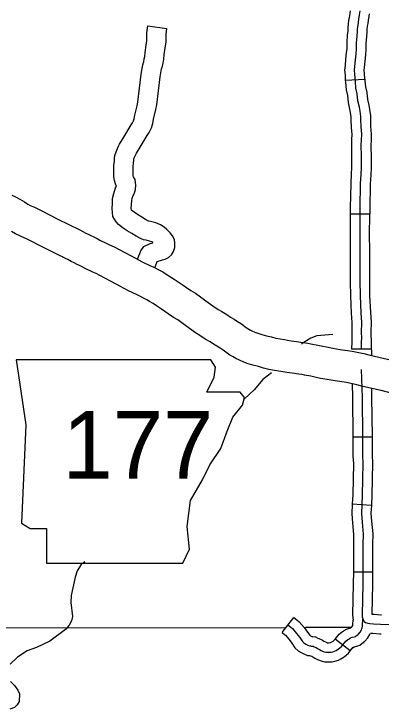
# Model space of a CAD drawing. Extents: x 1377389 to 1380723, y 1168351 to 1170484.
# Drawn here: x 1378723.7 to 1378781, y 1169308.4 to 1169417.1 of the extents above; entities that cross this region are included whole.
import ezdxf

# ---------------------------------------------------------------- set-up
doc = ezdxf.new("R2010")
doc.units = 0
doc.layers.add('B_Fill', color=7, linetype='Continuous')

msp = doc.modelspace()

# ---------------------------------------------------------------- linework, layer by layer
at = {"layer": 'B_Fill'}
for p, q in [((1378775.48, 1169406.7), (1378778.48, 1169406.87)), ((1378778.48, 1169406.87), (1378778.48, 1169406.87)), ((1378779.25, 1169385.74), (1378776.25, 1169385.76)), ((1378733.53, 1169383.52), (1378733.61, 1169383.48)), ((1378731.3, 1169379.05), (1378731.38, 1169379.01)), ((1378779.47, 1169364.62), (1378776.47, 1169364.66)), ((1378776.61, 1169350.92), (1378779.61, 1169350.92)), ((1378776.52, 1169340.44), (1378779.51, 1169340.28)), ((1378776.69, 1169329.83), (1378779.69, 1169329.81)), ((1378765.55, 1169320.37), (1378767.41, 1169322.72)), ((1378776.2, 1169317.48), (1378773.84, 1169319.33))]:
    msp.add_line(p, q, dxfattribs=at)
for points in [[(1378775.48, 1169406.7), (1378775.44, 1169407.5), (1378775.36, 1169408.26), (1378775.44, 1169409.01), (1378775.54, 1169409.97), (1378775.64, 1169410.95), (1378775.7, 1169411.64), (1378775.7, 1169412.61), (1378775.8, 1169413.73), (1378775.86, 1169414.39), (1378775.86, 1169414.81), (1378775.94, 1169415.51), (1378776.01, 1169416), (1378776.08, 1169416.47), (1378776.18, 1169417.14), (1378776.24, 1169417.52)], [(1378777.97, 1169364.64), (1378777.98, 1169365.8), (1378778, 1169366.4), (1378777.98, 1169367.27), (1378778, 1169368.83), (1378777.9, 1169370.33), (1378777.79, 1169373), (1378777.76, 1169375.35), (1378777.76, 1169378.87), (1378777.76, 1169380.2), (1378777.73, 1169382.39), (1378777.76, 1169386.73), (1378777.83, 1169390.48), (1378777.92, 1169391.99), (1378777.96, 1169392.97), (1378777.96, 1169393.66), (1378777.96, 1169394.69), (1378777.93, 1169396.58), (1378777.96, 1169397.34), (1378777.99, 1169398.24), (1378777.89, 1169399.4), (1378777.86, 1169400.53), (1378777.86, 1169401.03), (1378777.73, 1169401.85), (1378777.63, 1169402.49), (1378777.4, 1169403.45), (1378777.3, 1169404.54), (1378777.1, 1169405.44), (1378777, 1169406.5), (1378776.93, 1169407.63), (1378776.87, 1169408.26), (1378776.93, 1169408.85), (1378777.03, 1169409.82), (1378777.13, 1169410.81), (1378777.2, 1169411.57), (1378777.2, 1169412.54), (1378777.3, 1169413.6), (1378777.36, 1169414.33), (1378777.36, 1169414.72), (1378777.43, 1169415.32), (1378777.5, 1169415.79), (1378777.56, 1169416.25), (1378777.66, 1169416.91), (1378777.76, 1169417.54)], [(1378778.48, 1169406.87), (1378778.43, 1169407.75), (1378778.37, 1169408.25), (1378778.42, 1169408.69), (1378778.52, 1169409.66), (1378778.62, 1169410.67), (1378778.7, 1169411.51), (1378778.7, 1169412.47), (1378778.79, 1169413.46), (1378778.86, 1169414.26), (1378778.86, 1169414.64), (1378778.92, 1169415.13), (1378778.98, 1169415.57), (1378779.05, 1169416.03), (1378779.14, 1169416.69), (1378779.2, 1169417.06)], [(1378742.99, 1169378.69), (1378743.19, 1169379.23), (1378743.33, 1169379.61), (1378743.5, 1169380.04), (1378743.98, 1169380.68), (1378744.98, 1169381.14), (1378745.39, 1169381.27), (1378745.35, 1169381.3), (1378745.19, 1169381.4), (1378744.86, 1169381.54), (1378744.35, 1169381.67), (1378743.9, 1169381.76), (1378743.43, 1169381.96), (1378742.77, 1169382.3), (1378742.1, 1169382.71), (1378741.37, 1169383.16), (1378740.75, 1169383.57), (1378740, 1169384.11), (1378739.64, 1169384.56), (1378739.11, 1169385.41), (1378739.01, 1169386.63), (1378739.06, 1169387.41), (1378739.08, 1169388.19), (1378739.26, 1169388.98), (1378739.53, 1169389.88), (1378739.68, 1169390.13), (1378739.68, 1169390.15), (1378739.57, 1169390.32), (1378739.38, 1169391.01), (1378739.28, 1169391.58), (1378739.28, 1169392.31), (1378739.3, 1169393.34), (1378739.37, 1169394.03), (1378739.39, 1169394.47), (1378739.46, 1169394.91), (1378739.62, 1169395.5), (1378739.84, 1169396.04), (1378740.02, 1169396.38), (1378740.15, 1169396.69), (1378740.83, 1169397.78), (1378741.98, 1169399.71), (1378742.2, 1169400.02), (1378742.35, 1169400.34), (1378742.45, 1169400.65), (1378742.55, 1169401.23), (1378742.93, 1169402.71), (1378743.02, 1169403.27), (1378743.57, 1169407.61), (1378743.8, 1169409.1), (1378743.95, 1169409.64), (1378744.04, 1169410.02), (1378744.13, 1169410.4), (1378744.17, 1169411.02), (1378744.35, 1169412.16), (1378744.44, 1169412.85), (1378744.44, 1169413.39), (1378744.44, 1169414.1), (1378744.6, 1169415.21), (1378747.57, 1169414.77)], [(1378745.7, 1169377.37), (1378746, 1169378.2), (1378746.05, 1169378.33), (1378746.07, 1169378.34), (1378746.86, 1169378.59), (1378747.3, 1169378.71), (1378747.84, 1169378.98), (1378748.31, 1169379.4), (1378748.58, 1169379.9), (1378748.8, 1169380.56), (1378748.8, 1169381.21), (1378748.75, 1169381.78), (1378748.45, 1169382.37), (1378748.09, 1169382.85), (1378747.55, 1169383.36), (1378747.13, 1169383.73), (1378746.57, 1169384.08), (1378745.83, 1169384.38), (1378745.01, 1169384.6), (1378744.76, 1169384.65), (1378744.7, 1169384.68), (1378744.24, 1169384.91), (1378743.67, 1169385.26), (1378742.98, 1169385.69), (1378742.45, 1169386.04), (1378742.09, 1169386.3), (1378742.04, 1169386.38), (1378742.01, 1169386.67), (1378742.05, 1169387.26), (1378742.07, 1169387.82), (1378742.16, 1169388.23), (1378742.29, 1169388.66), (1378742.38, 1169388.8), (1378742.58, 1169389.26), (1378742.64, 1169389.62), (1378742.71, 1169390.26), (1378742.6, 1169391.15), (1378742.34, 1169391.56), (1378742.31, 1169391.67), (1378742.28, 1169391.85), (1378742.28, 1169392.27), (1378742.3, 1169393.16), (1378742.36, 1169393.8), (1378742.38, 1169394.16), (1378742.4, 1169394.3), (1378742.47, 1169394.55), (1378742.56, 1169394.76), (1378742.73, 1169395.09), (1378742.82, 1169395.31), (1378743.39, 1169396.22), (1378744.5, 1169398.07), (1378744.81, 1169398.52), (1378745.15, 1169399.26), (1378745.37, 1169399.93), (1378745.48, 1169400.6), (1378745.86, 1169402.09), (1378745.99, 1169402.82), (1378746.54, 1169407.2), (1378746.74, 1169408.46), (1378746.86, 1169408.9), (1378746.96, 1169409.34), (1378747.11, 1169409.97), (1378747.15, 1169410.69), (1378747.32, 1169411.73), (1378747.44, 1169412.66), (1378747.44, 1169413.39), (1378747.44, 1169413.88), (1378747.57, 1169414.77)], [(1378776.43, 1169396.28), (1378776.43, 1169396.6), (1378776.46, 1169397.4), (1378776.49, 1169398.2), (1378776.39, 1169399.31), (1378776.36, 1169400.51), (1378776.36, 1169400.91), (1378776.25, 1169401.62), (1378776.16, 1169402.19), (1378775.91, 1169403.2), (1378775.81, 1169404.31), (1378775.61, 1169405.2), (1378775.5, 1169406.38), (1378775.48, 1169406.7)], [(1378778.48, 1169406.87), (1378778.49, 1169406.61), (1378778.58, 1169405.67), (1378778.78, 1169404.77), (1378778.88, 1169403.69), (1378779.1, 1169402.78), (1378779.21, 1169402.09), (1378779.36, 1169401.14), (1378779.36, 1169400.55), (1378779.39, 1169399.49), (1378779.49, 1169398.28), (1378779.46, 1169397.28), (1378779.43, 1169396.56), (1378779.43, 1169396.33)], [(1378776.25, 1169385.76), (1378776.26, 1169386.75), (1378776.33, 1169390.54), (1378776.42, 1169392.06), (1378776.46, 1169393), (1378776.46, 1169393.67), (1378776.46, 1169394.68), (1378776.43, 1169396.28)], [(1378779.43, 1169396.33), (1378779.46, 1169394.7), (1378779.46, 1169393.66), (1378779.46, 1169392.94), (1378779.42, 1169391.92), (1378779.33, 1169390.42), (1378779.26, 1169386.71), (1378779.25, 1169385.74)], [(1378723.37, 1169388.72), (1378723.94, 1169388.46), (1378724.58, 1169388.11), (1378725.32, 1169387.66), (1378725.86, 1169387.33), (1378726.21, 1169387.13), (1378726.78, 1169386.87), (1378727.93, 1169386.32), (1378730.55, 1169384.99), (1378733.98, 1169383.29)], [(1378776.26, 1169375.17), (1378776.26, 1169375.34), (1378776.26, 1169378.87), (1378776.26, 1169380.18), (1378776.23, 1169382.38), (1378776.25, 1169385.76)], [(1378779.26, 1169375.21), (1378779.26, 1169375.36), (1378779.26, 1169378.87), (1378779.26, 1169380.21), (1378779.23, 1169382.39), (1378779.25, 1169385.74)], [(1378731.38, 1169379.01), (1378730.8, 1169379.28), (1378728.31, 1169380.52), (1378725.73, 1169381.83), (1378724.68, 1169382.33), (1378723.93, 1169382.67), (1378723.29, 1169383.04)], [(1378733.98, 1169383.29), (1378734.9, 1169382.8), (1378735.25, 1169382.62), (1378735.69, 1169382.41), (1378736.15, 1169382.2), (1378736.68, 1169381.92), (1378737.1, 1169381.69), (1378738.1, 1169381.21), (1378738.61, 1169380.98), (1378739.35, 1169380.63), (1378741.98, 1169379.23), (1378743.81, 1169378.25), (1378744.92, 1169377.72), (1378745.54, 1169377.44), (1378746.39, 1169377), (1378746.92, 1169376.71), (1378747.46, 1169376.38), (1378748.12, 1169375.97), (1378748.71, 1169375.58), (1378749.49, 1169375.06), (1378750.09, 1169374.66), (1378750.62, 1169374.28), (1378751.33, 1169373.81), (1378752.01, 1169373.38), (1378752.81, 1169372.83), (1378753.63, 1169372.2), (1378754.73, 1169371.41), (1378755.55, 1169370.86), (1378756.13, 1169370.51), (1378756.93, 1169370.04), (1378757.5, 1169369.67), (1378758.06, 1169369.34), (1378758.6, 1169368.98), (1378759.2, 1169368.59), (1378759.73, 1169368.2), (1378760.1, 1169367.93), (1378760.36, 1169367.79), (1378760.65, 1169367.63), (1378760.96, 1169367.48), (1378761.48, 1169367.25), (1378761.91, 1169367.09), (1378762.38, 1169366.94), (1378763.1, 1169366.75), (1378763.88, 1169366.55), (1378764.59, 1169366.37), (1378765.27, 1169366.24), (1378765.92, 1169366.13), (1378766.43, 1169366.03), (1378766.99, 1169365.96), (1378767.8, 1169365.85), (1378768.87, 1169365.7), (1378769.57, 1169365.6), (1378770.05, 1169365.5), (1378771.12, 1169365.29), (1378771.92, 1169365.1), (1378772.5, 1169365), (1378773.48, 1169364.81), (1378774.62, 1169364.61)], [(1378773.83, 1169359.68), (1378772.59, 1169359.89), (1378771.58, 1169360.08), (1378770.9, 1169360.21), (1378770.07, 1169360.4), (1378769.06, 1169360.6), (1378768.7, 1169360.67), (1378768.18, 1169360.75), (1378767.11, 1169360.89), (1378766.32, 1169361.01), (1378765.67, 1169361.09), (1378765.06, 1169361.2), (1378764.36, 1169361.32), (1378763.5, 1169361.49), (1378762.65, 1169361.7), (1378761.85, 1169361.91), (1378760.98, 1169362.13), (1378760.24, 1169362.37), (1378759.6, 1169362.62), (1378758.89, 1169362.92), (1378758.32, 1169363.2), (1378757.93, 1169363.42), (1378757.41, 1169363.7), (1378756.78, 1169364.17), (1378756.37, 1169364.47), (1378755.87, 1169364.79), (1378755.39, 1169365.11), (1378754.87, 1169365.42), (1378754.32, 1169365.77), (1378753.54, 1169366.23), (1378752.85, 1169366.66), (1378751.88, 1169367.3), (1378750.66, 1169368.18), (1378749.88, 1169368.77), (1378749.25, 1169369.21), (1378748.62, 1169369.61), (1378747.78, 1169370.15), (1378747.25, 1169370.54), (1378746.72, 1169370.89), (1378745.94, 1169371.41), (1378745.41, 1169371.77), (1378744.84, 1169372.12), (1378744.44, 1169372.37), (1378744.04, 1169372.59), (1378743.35, 1169372.94), (1378742.82, 1169373.18), (1378741.55, 1169373.78), (1378739.62, 1169374.82), (1378737.11, 1169376.16), (1378736.51, 1169376.45), (1378735.99, 1169376.68), (1378734.8, 1169377.25), (1378734.33, 1169377.51), (1378733.94, 1169377.71), (1378733.56, 1169377.89), (1378733.06, 1169378.13), (1378732.61, 1169378.35), (1378732.08, 1169378.64), (1378731.73, 1169378.82), (1378731.3, 1169379.05)], [(1378776.47, 1169364.66), (1378776.48, 1169365.83), (1378776.5, 1169366.4), (1378776.48, 1169367.27), (1378776.5, 1169368.79), (1378776.4, 1169370.25), (1378776.29, 1169372.96), (1378776.26, 1169375.17)], [(1378779.56, 1169363.65), (1378779.48, 1169367.28), (1378779.5, 1169368.87), (1378779.4, 1169370.41), (1378779.29, 1169373.04), (1378779.26, 1169375.21)], [(1378773.51, 1169366.93), (1378770.98, 1169366.73), (1378770.05, 1169366.39), (1378768.71, 1169365.52), (1378768.6, 1169365.42)], [(1378774.62, 1169364.61), (1378776.52, 1169364.33), (1378778.32, 1169363.95), (1378779.33, 1169363.7), (1378782.25, 1169363.04)], [(1378763.92, 1169360.94), (1378762.55, 1169359.88), (1378761.19, 1169358.27), (1378759.71, 1169356.87)], [(1378777.91, 1169361.47), (1378778.05, 1169357.11), (1378778.11, 1169350.98), (1378778.11, 1169347.97), (1378778.19, 1169346.83), (1378778.09, 1169341.81), (1378777.94, 1169338.94), (1378778.05, 1169337.62), (1378778.23, 1169335.7), (1378778.19, 1169334.1), (1378778.19, 1169330.13), (1378778.18, 1169327.92), (1378778.08, 1169323.14), (1378778.09, 1169322.81), (1378778.15, 1169322.5), (1378778.26, 1169322.26), (1378778.38, 1169322.09), (1378778.6, 1169321.92), (1378778.81, 1169321.85), (1378778.97, 1169321.79), (1378779.28, 1169321.76), (1378779.84, 1169321.72), (1378780.92, 1169321.63), (1378784.23, 1169321.56)], [(1378784.71, 1169357.16), (1378782.79, 1169357.72), (1378781.05, 1169358.19), (1378778.19, 1169358.83), (1378777.21, 1169359.07), (1378775.63, 1169359.41), (1378773.83, 1169359.68)], [(1378776.48, 1169359.23), (1378776.55, 1169357.08), (1378776.61, 1169350.98), (1378776.61, 1169350.92)], [(1378779.5, 1169358.54), (1378779.55, 1169357.14), (1378779.61, 1169350.99), (1378779.61, 1169350.92)], [(1378776.61, 1169350.92), (1378776.61, 1169347.92), (1378776.69, 1169346.79), (1378776.59, 1169341.87), (1378776.52, 1169340.44)], [(1378779.61, 1169350.92), (1378779.61, 1169348.03), (1378779.69, 1169346.87), (1378779.59, 1169341.76), (1378779.51, 1169340.28)], [(1378776.52, 1169340.44), (1378776.43, 1169338.92), (1378776.56, 1169337.49), (1378776.73, 1169335.65), (1378776.69, 1169334.12), (1378776.69, 1169330.14), (1378776.69, 1169329.83)], [(1378779.51, 1169340.28), (1378779.44, 1169338.97), (1378779.55, 1169337.76), (1378779.73, 1169335.75), (1378779.69, 1169334.09), (1378779.69, 1169330.13), (1378779.69, 1169329.81)], [(1378734.73, 1169331.42), (1378734.2, 1169330.96), (1378733.57, 1169330.01), (1378733.23, 1169329.02), (1378732.62, 1169326.12), (1378732.56, 1169325.02), (1378732.83, 1169322.83), (1378732.66, 1169322.2), (1378732.3, 1169321.51), (1378731.74, 1169320.84), (1378729.3, 1169319), (1378727.21, 1169318.02), (1378725.76, 1169317.46), (1378724.21, 1169316.49), (1378723.08, 1169315.4)], [(1378776.69, 1169329.83), (1378776.68, 1169327.94), (1378776.58, 1169323.13), (1378776.59, 1169322.65), (1378776.66, 1169322.3)], [(1378779.69, 1169329.81), (1378779.68, 1169327.9), (1378779.58, 1169323.24), (1378779.95, 1169323.21), (1378781, 1169323.13), (1378781.08, 1169323.13)], [(1378767.41, 1169322.72), (1378767.88, 1169322.35), (1378768.23, 1169322.04), (1378768.99, 1169321.15), (1378769.54, 1169320.41), (1378769.88, 1169319.91), (1378769.88, 1169319.91), (1378770, 1169319.84), (1378770.21, 1169319.73), (1378770.26, 1169319.73), (1378770.38, 1169319.7), (1378770.79, 1169319.66), (1378771.16, 1169319.48), (1378771.57, 1169319.31), (1378771.85, 1169319.14), (1378772.08, 1169319.01), (1378772.36, 1169318.87), (1378772.55, 1169318.78), (1378772.58, 1169318.76), (1378772.59, 1169318.76), (1378772.67, 1169318.76), (1378772.88, 1169318.76), (1378773.06, 1169318.77), (1378773.12, 1169318.78), (1378773.16, 1169318.79), (1378773.23, 1169318.83), (1378773.55, 1169319.02), (1378773.64, 1169319.09), (1378773.71, 1169319.15), (1378773.84, 1169319.33)], [(1378766.48, 1169321.54), (1378766.92, 1169321.2), (1378767.16, 1169320.99), (1378767.82, 1169320.21), (1378768.31, 1169319.55), (1378768.73, 1169318.94), (1378768.97, 1169318.71), (1378769.27, 1169318.52), (1378769.59, 1169318.36), (1378769.86, 1169318.26), (1378770.02, 1169318.24), (1378770.12, 1169318.22), (1378770.39, 1169318.19), (1378770.56, 1169318.11), (1378770.88, 1169317.98), (1378771.09, 1169317.84), (1378771.39, 1169317.68), (1378771.68, 1169317.54), (1378771.96, 1169317.39), (1378772.2, 1169317.31), (1378772.4, 1169317.27), (1378772.62, 1169317.26), (1378772.91, 1169317.26), (1378773.21, 1169317.27), (1378773.46, 1169317.31), (1378773.77, 1169317.41), (1378773.99, 1169317.54), (1378774.39, 1169317.78), (1378774.6, 1169317.94), (1378774.82, 1169318.14), (1378775.49, 1169319)], [(1378774.45, 1169320.1), (1378775.02, 1169320.5), (1378775.14, 1169320.57), (1378775.25, 1169320.65), (1378775.64, 1169320.86), (1378776.1, 1169321.04), (1378776.32, 1169321.09), (1378776.36, 1169321.12), (1378776.52, 1169321.31), (1378776.6, 1169321.43), (1378776.61, 1169321.47), (1378776.62, 1169321.56), (1378776.63, 1169321.64), (1378776.66, 1169322.3)], [(1378775.49, 1169319), (1378775.84, 1169319.25), (1378775.96, 1169319.32), (1378776.03, 1169319.37), (1378776.27, 1169319.5), (1378776.53, 1169319.6), (1378776.85, 1169319.67), (1378777, 1169319.72), (1378777.14, 1169319.81), (1378777.42, 1169320.05), (1378777.73, 1169320.41), (1378777.97, 1169320.79), (1378778.02, 1169320.95), (1378778.05, 1169321.04), (1378778.08, 1169321.21), (1378778.1, 1169321.3), (1378778.13, 1169321.49), (1378778.16, 1169322.46)], [(1378718.08, 1169321.08), (1378766.19, 1169321.15)], [(1378769.23, 1169321.16), (1378776.43, 1169321.17)], [(1378765.55, 1169320.37), (1378765.95, 1169320.05), (1378766.09, 1169319.93), (1378766.65, 1169319.28), (1378767.09, 1169318.68), (1378767.57, 1169317.96), (1378768.05, 1169317.51), (1378768.54, 1169317.21), (1378768.97, 1169316.99), (1378769.51, 1169316.78), (1378769.77, 1169316.76), (1378769.86, 1169316.74), (1378769.99, 1169316.72), (1378770.19, 1169316.64), (1378770.34, 1169316.55), (1378770.69, 1169316.36), (1378770.99, 1169316.2), (1378771.37, 1169316.01), (1378771.81, 1169315.86), (1378772.2, 1169315.78), (1378772.58, 1169315.76), (1378772.95, 1169315.76), (1378773.36, 1169315.78), (1378773.8, 1169315.85), (1378774.37, 1169316.02), (1378774.76, 1169316.25), (1378775.23, 1169316.53), (1378775.57, 1169316.79), (1378775.93, 1169317.12), (1378776.2, 1169317.48)], [(1378773.84, 1169319.33), (1378774.45, 1169320.1)], [(1378776.36, 1169317.78), (1378776.67, 1169318), (1378776.78, 1169318.06), (1378776.82, 1169318.09), (1378776.9, 1169318.13), (1378776.96, 1169318.16), (1378777.25, 1169318.22), (1378777.68, 1169318.37), (1378778.04, 1169318.61), (1378778.47, 1169318.98), (1378778.94, 1169319.51), (1378779.33, 1169320.13)], [(1378779.36, 1169320.25), (1378779.73, 1169320.22), (1378780.85, 1169320.13), (1378781.02, 1169320.13)], [(1378776.2, 1169317.48), (1378776.68, 1169318.08)], [(1378723.16, 1169312.7), (1378723.75, 1169312.06), (1378724.27, 1169311.31), (1378724.52, 1169310.77), (1378724.47, 1169309.55), (1378724.2, 1169309.04), (1378723.77, 1169308.61), (1378723.01, 1169308.38)]]:
    msp.add_lwpolyline(points, dxfattribs=at)
msp.add_lwpolyline([(1378724.01, 1169362.99), (1378725.53, 1169352.84), (1378724.86, 1169337.44), (1378726.21, 1169336.6), (1378728.75, 1169336.6), (1378728.75, 1169331.18), (1378750.06, 1169331.18), (1378751.08, 1169333.38), (1378750.74, 1169336.94), (1378751.25, 1169341), (1378753.11, 1169344.21), (1378754.29, 1169346.58), (1378755.99, 1169349.12), (1378757, 1169351.82), (1378757.85, 1169354.02), (1378759.37, 1169355.88), (1378759.71, 1169357.07), (1378759.03, 1169357.91), (1378753.79, 1169357.91), (1378754.97, 1169360.28), (1378755.14, 1169361.81), (1378754.44, 1169362.98)], close=True, dxfattribs=at)

# ---------------------------------------------------------------- texts
msp.add_text('177', height=10.56, dxfattribs=at).set_placement((1378731.26, 1169344.42))

doc.saveas('drawing.dxf')
